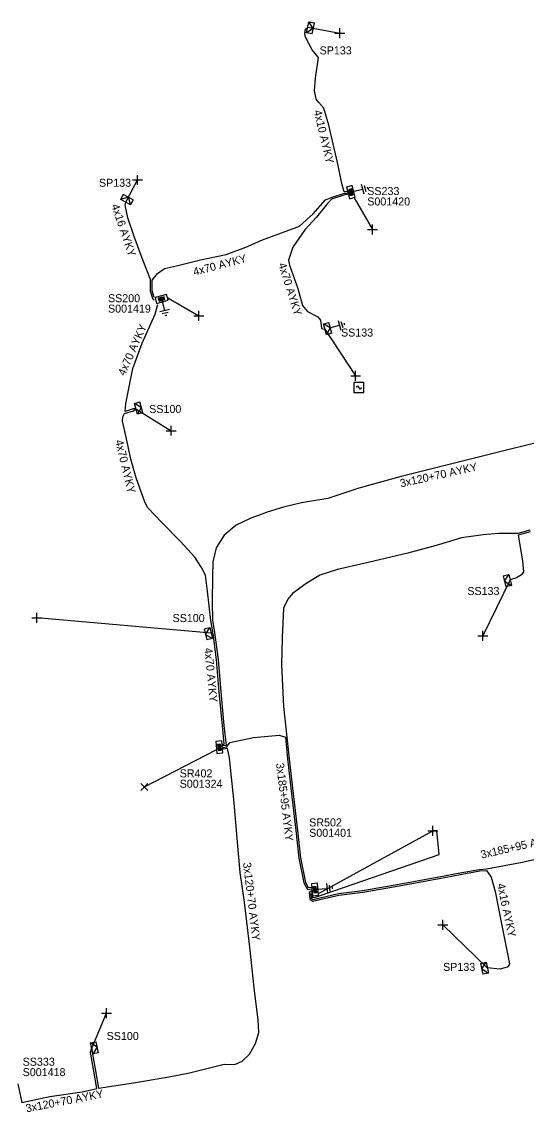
# Model space of a CAD drawing. Extents: x -763093 to -760976, y -1155572 to -1152009.
# Drawn here: x -762349.6 to -762286.6, y -1154687.4 to -1154551.2 of the extents above; entities that cross this region are included whole.
import ezdxf

# ---------------------------------------------------------------- set-up
doc = ezdxf.new("R2010")
doc.units = 0
for name, color, linetype in [('Vrstva 1', 7, 'Continuous'), ('Vrstva 14', 7, 'Continuous'), ('Vrstva 15', 7, 'Continuous'), ('Vrstva 28', 7, 'Continuous'), ('Vrstva 29', 7, 'Continuous'), ('Vrstva 30', 7, 'Continuous'), ('Vrstva 31', 7, 'Continuous'), ('Vrstva 33', 7, 'Continuous'), ('Vrstva 34', 7, 'Continuous'), ('Vrstva 5', 7, 'Continuous'), ('Vrstva 59', 7, 'Continuous'), ('Vrstva 6', 7, 'Continuous'), ('Vrstva 8', 7, 'Continuous'), ('Vrstva 9', 7, 'Continuous')]:
    doc.layers.add(name, color=color, linetype=linetype)

# ---------------------------------------------------------------- blocks, each defined once
blk = doc.blocks.new('NN800')
at = {"layer": 'Vrstva 1'}
for points in [[(-0.44, 0.44), (0.44, -0.44)], [(-0.44, -0.44), (0.44, 0.44)]]:
    blk.add_lwpolyline(points, dxfattribs=at)
blk = doc.blocks.new('NN620')
at = {"layer": 'Vrstva 8'}
for points in [[(0.75, 0), (-0.75, 0)], [(-0.75, 0), (-0.75, -0.75)], [(0.75, -0.75), (0.75, 0)], [(-0.75, -0.75), (0.75, -0.75)], [(0.37, -0.18), (-0.38, -0.18)], [(-0.38, -0.18), (-0.38, -0.56)], [(-0.38, -0.56), (0.37, -0.56)], [(0.32, -0.23), (-0.33, -0.23)], [(-0.33, -0.23), (-0.33, -0.51)], [(-0.33, -0.51), (0.32, -0.51)], [(0.27, -0.27), (-0.28, -0.27)], [(-0.28, -0.27), (-0.28, -0.46)], [(-0.28, -0.46), (0.27, -0.46)], [(0.23, -0.32), (-0.23, -0.32)], [(-0.23, -0.32), (-0.23, -0.42)], [(-0.23, -0.42), (0.23, -0.42)], [(-0.19, -0.37), (0.19, -0.37)], [(0.23, -0.42), (0.23, -0.32)], [(0.27, -0.46), (0.27, -0.27)], [(0.32, -0.51), (0.32, -0.23)], [(0.37, -0.56), (0.37, -0.18)]]:
    blk.add_lwpolyline(points, dxfattribs=at)
blk = doc.blocks.new('NN630')
at = {"layer": 'Vrstva 9'}
for points in [[(0, -0.7), (-0.7, 0)], [(-0.7, -0.7), (-0.7, 0), (0.7, 0), (0.7, -0.7)], [(-0.7, -0.7), (0.7, -0.7)], [(0, -0.7), (0.7, 0)]]:
    blk.add_lwpolyline(points, dxfattribs=at)
blk = doc.blocks.new('NN810')
at = {"layer": 'Vrstva 14'}
for points in [[(0, -0.64), (0, -1.89)], [(0.63, -1.89), (-0.62, -1.89)], [(0.39, -2.2), (-0.4, -2.2)], [(0, -2.52), (-0.12, -2.52)], [(0.14, -2.52), (0, -2.52)]]:
    blk.add_lwpolyline(points, dxfattribs=at)
blk = doc.blocks.new('NN740')
at = {"layer": 'Vrstva 1'}
for points in [[(0.62, 0.62), (-0.63, 0.62)], [(-0.63, 0.62), (-0.63, -0.63)], [(0, 0), (0, 0.01), (0, 0.03), (-0.01, 0.05), (-0.01, 0.06), (-0.02, 0.08), (-0.03, 0.09), (-0.04, 0.1), (-0.05, 0.11), (-0.06, 0.12), (-0.08, 0.13), (-0.09, 0.14), (-0.11, 0.14), (-0.12, 0.15), (-0.14, 0.15), (-0.15, 0.15), (-0.17, 0.15), (-0.18, 0.15), (-0.2, 0.15), (-0.21, 0.14), (-0.23, 0.13), (-0.24, 0.12), (-0.26, 0.11), (-0.27, 0.1), (-0.28, 0.09), (-0.29, 0.08), (-0.29, 0.06), (-0.3, 0.05), (-0.3, 0.03), (-0.31, 0.02), (-0.31, 0), (-0.31, 0)], [(0.62, -0.63), (0.62, 0.62)], [(-0.63, -0.63), (0.62, -0.63)], [(0, 0), (0, -0.02), (0, -0.03), (0.01, -0.05), (0.01, -0.06), (0.02, -0.08), (0.03, -0.09), (0.04, -0.1), (0.05, -0.11), (0.06, -0.12), (0.07, -0.13), (0.09, -0.14), (0.1, -0.15), (0.12, -0.15), (0.13, -0.15), (0.15, -0.15), (0.16, -0.15), (0.18, -0.15), (0.19, -0.15), (0.21, -0.14), (0.22, -0.14), (0.24, -0.13), (0.25, -0.12), (0.26, -0.11), (0.27, -0.09), (0.28, -0.08), (0.29, -0.07), (0.29, -0.05), (0.3, -0.04), (0.3, -0.02), (0.3, -0.01), (0.3, -0.01)]]:
    blk.add_lwpolyline(points, dxfattribs=at)

msp = doc.modelspace()

# ---------------------------------------------------------------- linework, layer by layer
at = {"layer": 'Vrstva 5'}
for points in [[(-762309, -1154572.36), (-762309.33, -1154572.39), (-762309.59, -1154571.52), (-762310.16, -1154568.76), (-762311.23, -1154564.07), (-762311.86, -1154561.95), (-762312.49, -1154561.26), (-762312.84, -1154560.82), (-762313.02, -1154559.8), (-762312.9, -1154558.22), (-762312.53, -1154555.63), (-762313.31, -1154554.67), (-762314.15, -1154553.09), (-762314.25, -1154552.69), (-762314.17, -1154552.07), (-762313.88, -1154551.85)], [(-762333.07, -1154585.6), (-762333.33, -1154584.77), (-762333.32, -1154583.46), (-762332.67, -1154582.62), (-762331.78, -1154581.99), (-762330.27, -1154581.64), (-762327.29, -1154580.91), (-762324.06, -1154580.23), (-762321.6, -1154579.31), (-762319.52, -1154578.4), (-762317.5, -1154577.67), (-762314.93, -1154576.69), (-762313.19, -1154575.14), (-762311.68, -1154573.42), (-762310.82, -1154573.07), (-762309.27, -1154572.59), (-762308.94, -1154572.56)], [(-762308.9, -1154572.76), (-762309.25, -1154572.79), (-762310.92, -1154573.32), (-762311.58, -1154574.06), (-762312.79, -1154575.57), (-762314.23, -1154577.15), (-762315.75, -1154579.34), (-762316.27, -1154580.94), (-762316.17, -1154581.56), (-762315.11, -1154584.5), (-762314.53, -1154586.61), (-762313.93, -1154587.34), (-762312.6, -1154588.04), (-762312.27, -1154588.44), (-762312.14, -1154589.5), (-762311.74, -1154589.58)], [(-762333.08, -1154585.96), (-762333.2, -1154585.86), (-762333.53, -1154584.81), (-762333.52, -1154583.35), (-762334.45, -1154581.05), (-762335.57, -1154578.01), (-762336.39, -1154575.67), (-762336.71, -1154574.07), (-762336.64, -1154573.7)], [(-762324.51, -1154641.45), (-762324.31, -1154641.41), (-762324.55, -1154639.11), (-762324.94, -1154634.88), (-762325.29, -1154630.87), (-762325.71, -1154627.59), (-762325.97, -1154627.53), (-762325.74, -1154627.39), (-762326, -1154625.96), (-762326.43, -1154622.32), (-762326.67, -1154620.32), (-762327.15, -1154619.34), (-762328, -1154618.04), (-762329.78, -1154616.09), (-762332.14, -1154613.73), (-762333.86, -1154611.9), (-762334.26, -1154611.2), (-762335.32, -1154608.14), (-762335.98, -1154605.81), (-762336.56, -1154603.07), (-762337.02, -1154601.04), (-762337, -1154600.5), (-762336.77, -1154600.1), (-762335.65, -1154599.76), (-762335.36, -1154599.53), (-762335.71, -1154599.54), (-762336.69, -1154599.86), (-762336.61, -1154598.87), (-762335.73, -1154594.49), (-762334.56, -1154591.31), (-762332.95, -1154587.68), (-762332.67, -1154586.6), (-762332.6, -1154586.47)], [(-762284.83, -1154603.65), (-762290.55, -1154605.05), (-762296.35, -1154606.51), (-762302.2, -1154607.97), (-762307.49, -1154609.45), (-762311.38, -1154610.72), (-762314.66, -1154611.26), (-762316.93, -1154611.79), (-762318.97, -1154612.43), (-762321.07, -1154613.22), (-762322.82, -1154614.05), (-762324.34, -1154615.31), (-762325.31, -1154616.89), (-762325.73, -1154618.62), (-762325.8, -1154620.42), (-762325.82, -1154623.58), (-762325.8, -1154625.92), (-762325.52, -1154627.45), (-762325.09, -1154630.85), (-762324.74, -1154634.86), (-762324.35, -1154639.09), (-762324.09, -1154641.57), (-762324.49, -1154641.64)], [(-762286.11, -1154614.67), (-762287.63, -1154615.11), (-762290.05, -1154615.11), (-762291.97, -1154615.27), (-762294.66, -1154615.64), (-762297.54, -1154616.5), (-762301.35, -1154617.55), (-762306.87, -1154618.83), (-762310.17, -1154619.58), (-762312.36, -1154620.28), (-762314.12, -1154621.39), (-762315.8, -1154622.58), (-762316.37, -1154623.28), (-762316.89, -1154624.42), (-762317.07, -1154628.15), (-762317.15, -1154631.5), (-762316.9, -1154636.71), (-762316.48, -1154640.55), (-762316.22, -1154643.24), (-762315.68, -1154647.97), (-762315.15, -1154652.18), (-762314.78, -1154655.63), (-762314.18, -1154658.68), (-762313.84, -1154659.33), (-762313.41, -1154659.28)], [(-762286.07, -1154614.87), (-762287.58, -1154615.31), (-762287.04, -1154618.51), (-762286.92, -1154619.88), (-762287.15, -1154620.27), (-762287.77, -1154620.64), (-762288.59, -1154620.9)], [(-762324.47, -1154641.85), (-762324, -1154641.76), (-762323.6, -1154641.21), (-762320.68, -1154640.59), (-762317.44, -1154640.27), (-762316.68, -1154640.52), (-762316.42, -1154643.26), (-762315.88, -1154647.99), (-762315.35, -1154652.2), (-762314.98, -1154655.65), (-762314.38, -1154658.74), (-762313.93, -1154659.58), (-762313.4, -1154659.5)], [(-762350.14, -1154683.86), (-762349.62, -1154686.18), (-762346.13, -1154685.44), (-762342.07, -1154684.84), (-762340.24, -1154684.42), (-762340.61, -1154682.27), (-762341.03, -1154679.89), (-762340.88, -1154679.41), (-762340.83, -1154679.89), (-762340.41, -1154682.23), (-762340.04, -1154684.39), (-762335.66, -1154683.73), (-762331.47, -1154683.03), (-762328.67, -1154682.49), (-762324.34, -1154681.39), (-762322.98, -1154681.42), (-762322.09, -1154681.02), (-762321.15, -1154680.16), (-762320.4, -1154678.83), (-762320, -1154677.44), (-762320.06, -1154675.84), (-762320.57, -1154671.9), (-762320.71, -1154670.65), (-762321.11, -1154666.78), (-762321.8, -1154661.16), (-762322.31, -1154657.44), (-762322.71, -1154653.14), (-762323.06, -1154648.76), (-762323.65, -1154643.13), (-762323.91, -1154641.94), (-762324.45, -1154642.04)], [(-762313.34, -1154659.98), (-762313.5, -1154660.09), (-762313.44, -1154660.66), (-762313.22, -1154660.83), (-762310.04, -1154660.09), (-762307.02, -1154659.7), (-762302.93, -1154658.98), (-762297.49, -1154657.98), (-762294.86, -1154657.51), (-762292.39, -1154657.06), (-762291.54, -1154656.98), (-762287.28, -1154656.21), (-762283.69, -1154655.4), (-762281.21, -1154655.08), (-762280.96, -1154654.76), (-762281.64, -1154651.83), (-762281.38, -1154650.65), (-762280.66, -1154650.04), (-762279.42, -1154649.62), (-762277.12, -1154649.34), (-762274.23, -1154648.79), (-762272.2, -1154648.23), (-762271.91, -1154649.18)], [(-762313.37, -1154659.75), (-762313.72, -1154659.94), (-762313.62, -1154660.76), (-762313.28, -1154661.05), (-762310, -1154660.29), (-762306.98, -1154659.9), (-762302.89, -1154659.18), (-762297.45, -1154658.18), (-762294.82, -1154657.71), (-762292.37, -1154657.26), (-762291.52, -1154657.18), (-762290.93, -1154658.03), (-762290.45, -1154659.82), (-762289.65, -1154663.85), (-762288.64, -1154668.84), (-762288.81, -1154669.22), (-762289.81, -1154669.54), (-762291.44, -1154669.34)]]:
    msp.add_lwpolyline(points, dxfattribs=at)
at = {"layer": 'Vrstva 59'}
for points in [[(-762313.88, -1154551.85), (-762309.87, -1154552.57)], [(-762336.64, -1154573.7), (-762335.15, -1154570.93)], [(-762308.06, -1154573.14), (-762305.78, -1154577.13)], [(-762331.37, -1154585.66), (-762327.51, -1154587.9)], [(-762311.74, -1154589.58), (-762307.89, -1154595.38)], [(-762335.36, -1154599.53), (-762330.94, -1154602.25)], [(-762288.59, -1154620.9), (-762292, -1154627.88)], [(-762325.97, -1154627.53), (-762347.75, -1154625.63)], [(-762325.37, -1154642.17), (-762334.31, -1154646.78)], [(-762312.47, -1154660.03), (-762298.25, -1154652.26)], [(-762291.44, -1154669.34), (-762297, -1154664)], [(-762340.88, -1154679.41), (-762339.03, -1154675.02)]]:
    msp.add_lwpolyline(points, dxfattribs=at)
at = {"layer": 'Vrstva 9'}
msp.add_lwpolyline([(-762313.33, -1154660.14), (-762313.27, -1154660.58), (-762312.92, -1154660.52), (-762297.44, -1154655.21), (-762297.73, -1154652.24), (-762298.25, -1154652.26)], dxfattribs=at)

# ---------------------------------------------------------------- block references
at = {"layer": 'Vrstva 15'}
for p, rotation in [((-762308.85, -1154572.55), 104.95918885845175), ((-762332.24, -1154585.43), 13.962789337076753), ((-762311.74, -1154589.58), 105.51481113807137), ((-762313.34, -1154659.61), 95.41604442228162)]:
    msp.add_blockref('NN810', p, dxfattribs=dict(at, rotation=rotation))
at = {"layer": 'Vrstva 28'}
for p, rotation in [((-762308.85, -1154572.55), 104.95918885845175), ((-762332.24, -1154585.43), 15.053236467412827), ((-762324.56, -1154641.76), -83.97462306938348), ((-762313.34, -1154659.61), 95.41604443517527)]:
    msp.add_blockref('NN620', p, dxfattribs=dict(at, rotation=rotation))
at = {"layer": 'Vrstva 31'}
for p, rotation in [((-762313.88, -1154551.85), 78.56006109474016), ((-762336.64, -1154573.7), 152.83360555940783), ((-762311.74, -1154589.58), 105.51481113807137), ((-762335.36, -1154599.53), 105.78855001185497), ((-762288.59, -1154620.9), -75.85464716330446), ((-762325.97, -1154627.53), -76.33004998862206), ((-762291.44, -1154669.34), -78.13180002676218), ((-762340.88, -1154679.41), 101.32802497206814)]:
    msp.add_blockref('NN630', p, dxfattribs=dict(at, rotation=rotation))
at = {"layer": 'Vrstva 34'}
for p, rotation in [((-762309.87, -1154552.57), 45), ((-762335.15, -1154570.93), 45), ((-762305.78, -1154577.13), 45.00000009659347), ((-762327.51, -1154587.91), 45), ((-762307.89, -1154595.38), 45.00000009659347), ((-762330.94, -1154602.25), 44.99999995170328), ((-762347.75, -1154625.63), 45), ((-762292, -1154627.88), 45), ((-762298.25, -1154652.26), 45), ((-762297, -1154664), 45), ((-762339.03, -1154675.02), 45)]:
    msp.add_blockref('NN800', p, dxfattribs=dict(at, rotation=rotation))
for name, p in [('NN740', (-762307.48, -1154596.86)), ('NN800', (-762334.31, -1154646.78))]:
    msp.add_blockref(name, p, dxfattribs=at)

# ---------------------------------------------------------------- texts
at = {"layer": 'Vrstva 29'}
for s, p in [('S001420', (-762306.44, -1154574.11)), ('S001419', (-762338.85, -1154587.5)), ('S001324', (-762329.89, -1154646.86)), ('S001401', (-762313.7, -1154652.99)), ('S001418', (-762349.52, -1154682.89))]:
    msp.add_text(s, height=1, dxfattribs=at).set_placement(p)
at = {"layer": 'Vrstva 30'}
for s, p in [('SS233', (-762306.44, -1154572.81)), ('SS200', (-762338.85, -1154586.2)), ('SR402', (-762329.89, -1154645.56)), ('SR502', (-762313.7, -1154651.69)), ('SS333', (-762349.52, -1154681.59))]:
    msp.add_text(s, height=1, dxfattribs=at).set_placement(p)
at = {"layer": 'Vrstva 33'}
for s, p in [('SP133', (-762312.4, -1154555.24)), ('SP133', (-762339.98, -1154571.78)), ('SS133', (-762309.72, -1154590.49)), ('SS100', (-762333.7, -1154600.04)), ('SS133', (-762293.93, -1154622.78)), ('SS100', (-762330.78, -1154626.16)), ('SP133', (-762296.96, -1154669.74)), ('SS100', (-762339.02, -1154678.37))]:
    msp.add_text(s, height=1, dxfattribs=at).set_placement(p)
at = {"layer": 'Vrstva 6'}
for s, rotation, p in [('4x10 AYKY', 283.327, (-762313.14, -1154562.3)), ('4x16 AYKY', 288.711, (-762338.45, -1154574.11)), ('4x70 AYKY', 14.782, (-762328.06, -1154582.9)), ('4x70 AYKY', 287.279, (-762317.57, -1154581.44)), ('4x70 AYKY', 66.08, (-762336.75, -1154595.47)), ('4x70 AYKY', 283.669, (-762337.96, -1154603.51)), ('3x120+70 AYKY', 12.443, (-762302.23, -1154609.33)), ('4x70 AYKY', 275.55, (-762326.8, -1154629.42)), ('3x185+95 AYKY', 276.981, (-762317.85, -1154643.81)), ('3x185+95 AYKY', 12.867, (-762292.14, -1154655.72)), ('3x120+70 AYKY', 276.914, (-762321.98, -1154656.24)), ('4x16 AYKY', 282.081, (-762290.22, -1154658.91)), ('3x120+70 AYKY', 10.975, (-762349.03, -1154687.42))]:
    msp.add_text(s, height=1, rotation=rotation, dxfattribs=at).set_placement(p)

doc.saveas('drawing.dxf')
